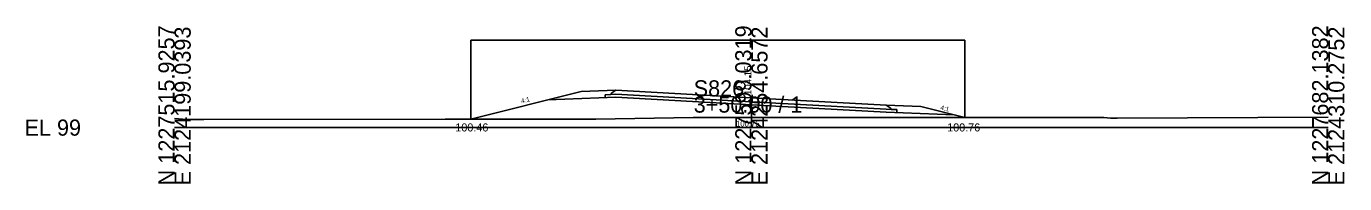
# Model space of a CAD drawing. Extents: x 2118382 to 2118616, y 1213030 to 1222057.
# Drawn here: x 2118381.9 to 2118610.4, y 1214030.1 to 1214057.3 of the extents above; entities that cross this region are included whole.
import ezdxf

# ---------------------------------------------------------------- set-up
doc = ezdxf.new("R2010")
doc.units = 0
for name, color, linetype in [('XS_CELL', 7, 'Continuous'), ('XS_M_DITCH', 7, 'Continuous'), ('XS_P_FINISHED_GRADE', 7, 'Continuous'), ('XS_P_FINISHED_GRADE_ELEV_TX', 7, 'Continuous'), ('XS_P_SUBGRADE_GRANULAR', 7, 'Continuous'), ('XS_P_SUBGRADE_PAVEMENT', 7, 'Continuous'), ('XS_P_TX_DCH', 7, 'Continuous'), ('XS_P_TX_FS_BS', 7, 'Continuous'), ('XS_X_GROUND', 7, 'Continuous'), ('XS_X_GROUND_TX', 7, 'Continuous')]:
    doc.layers.add(name, color=color, linetype=linetype)

msp = doc.modelspace()

# ---------------------------------------------------------------- linework, layer by layer
at = {"layer": 'XS_CELL'}
for p, q in [((2118507.6, 1214039.8), (2118507.6, 1214045.19)), ((2118407.6, 1214039.8), (2118507.6, 1214039.8)), ((2118507.6, 1214039.8), (2118607.6, 1214039.8))]:
    msp.add_line(p, q, dxfattribs=at)
at = {"layer": 'XS_M_DITCH'}
for p, q in [((2118458.97, 1214041.26), (2118458.97, 1214054.95)), ((2118458.97, 1214054.95), (2118544.58, 1214054.95)), ((2118544.58, 1214054.95), (2118544.58, 1214041.56))]:
    msp.add_line(p, q, dxfattribs=at)
at = {"layer": 'XS_P_FINISHED_GRADE'}
for p, q in [((2118478.08, 1214046.04), (2118458.97, 1214041.26)), ((2118484.08, 1214046.28), (2118478.08, 1214046.04)), ((2118484.08, 1214046.28), (2118507.6, 1214044.95)), ((2118507.6, 1214044.95), (2118530.98, 1214043.7)), ((2118530.98, 1214043.7), (2118536.98, 1214043.46)), ((2118536.98, 1214043.46), (2118544.58, 1214041.56))]:
    msp.add_line(p, q, dxfattribs=at)
at = {"layer": 'XS_P_SUBGRADE_GRANULAR'}
for p, q in [((2118483.24, 1214045.54), (2118482.24, 1214045.5)), ((2118482.24, 1214045), (2118482.24, 1214045.5)), ((2118484.08, 1214045.07), (2118472.32, 1214044.6)), ((2118484.08, 1214045.07), (2118507.6, 1214043.74)), ((2118507.6, 1214043.74), (2118530.98, 1214042.49)), ((2118531.83, 1214042.96), (2118532.83, 1214042.92)), ((2118532.83, 1214042.42), (2118532.83, 1214042.92)), ((2118530.98, 1214042.49), (2118542.74, 1214042.02))]:
    msp.add_line(p, q, dxfattribs=at)
at = {"layer": 'XS_P_SUBGRADE_PAVEMENT'}
for p, q in [((2118483.39, 1214045.8), (2118483.24, 1214045.54)), ((2118484.08, 1214045.57), (2118483.24, 1214045.54)), ((2118484.08, 1214046.28), (2118483.39, 1214045.8)), ((2118484.08, 1214045.57), (2118507.6, 1214044.24)), ((2118507.6, 1214044.24), (2118530.98, 1214042.99)), ((2118530.98, 1214043.7), (2118531.68, 1214043.21)), ((2118530.98, 1214042.99), (2118531.83, 1214042.96)), ((2118531.68, 1214043.21), (2118531.83, 1214042.96))]:
    msp.add_line(p, q, dxfattribs=at)
at = {"layer": 'XS_X_GROUND'}
for p, q in [((2118407.6, 1214041.36), (2118409.65, 1214041.2)), ((2118409.65, 1214041.2), (2118409.95, 1214041.18)), ((2118409.95, 1214041.18), (2118412.66, 1214041.18)), ((2118412.66, 1214041.18), (2118454.54, 1214041.25)), ((2118454.54, 1214041.26), (2118455.59, 1214041.27)), ((2118455.59, 1214041.27), (2118468.15, 1214041.26)), ((2118468.15, 1214041.26), (2118479.47, 1214041.25)), ((2118479.47, 1214041.25), (2118480.64, 1214041.26)), ((2118480.64, 1214041.26), (2118497.53, 1214041.55)), ((2118497.53, 1214041.55), (2118507.6, 1214041.55)), ((2118507.6, 1214041.55), (2118566.17, 1214041.56)), ((2118566.17, 1214041.56), (2118568.72, 1214041.57)), ((2118568.72, 1214041.57), (2118569.85, 1214041.42)), ((2118569.85, 1214041.42), (2118571.01, 1214041.43)), ((2118571.01, 1214041.43), (2118607.6, 1214041.6))]:
    msp.add_line(p, q, dxfattribs=at)

# ---------------------------------------------------------------- texts
at = {"layer": 'XS_CELL'}
for s, p in [('N 1227515.9257', (2118407.6, 1214029.8)), ('E 2124199.0393', (2118410.4, 1214029.8)), ('N 1227599.0319', (2118507.6, 1214029.8)), ('E 2124254.6572', (2118510.4, 1214029.8)), ('N 1227682.1382', (2118607.6, 1214029.8)), ('E 2124310.2752', (2118610.4, 1214029.8))]:
    msp.add_text(s, height=2.8, rotation=90, dxfattribs=at).set_placement(p)
for s, p in [('S826', (2118497.6, 1214045.19)), ('3+50.00 / 1', (2118497.6, 1214042.39)), ('EL 99', (2118381.6, 1214038.4))]:
    msp.add_text(s, height=2.8, dxfattribs=at).set_placement(p)
at = {"layer": 'XS_P_FINISHED_GRADE_ELEV_TX'}
msp.add_text(' 104.15', height=1.25, rotation=90, dxfattribs=at).set_placement((2118507.6, 1214044.96))
at = {"layer": 'XS_P_TX_DCH'}
for s, p in [('100.46', (2118456.27, 1214039.13)), ('100.76', (2118541.54, 1214039.13))]:
    msp.add_text(s, height=1.4, dxfattribs=at).set_placement(p)
at = {"layer": 'XS_P_TX_FS_BS'}
for rotation, p in [(14.0362, (2118467.77, 1214043.99)), (345.9638, (2118540.3, 1214042.93))]:
    msp.add_text('4:1', height=0.8, rotation=rotation, dxfattribs=at).set_placement(p)
at = {"layer": 'XS_X_GROUND_TX'}
msp.add_text('100.75', height=1, dxfattribs=at).set_placement((2118504.93, 1214039.99))

doc.saveas('drawing.dxf')
